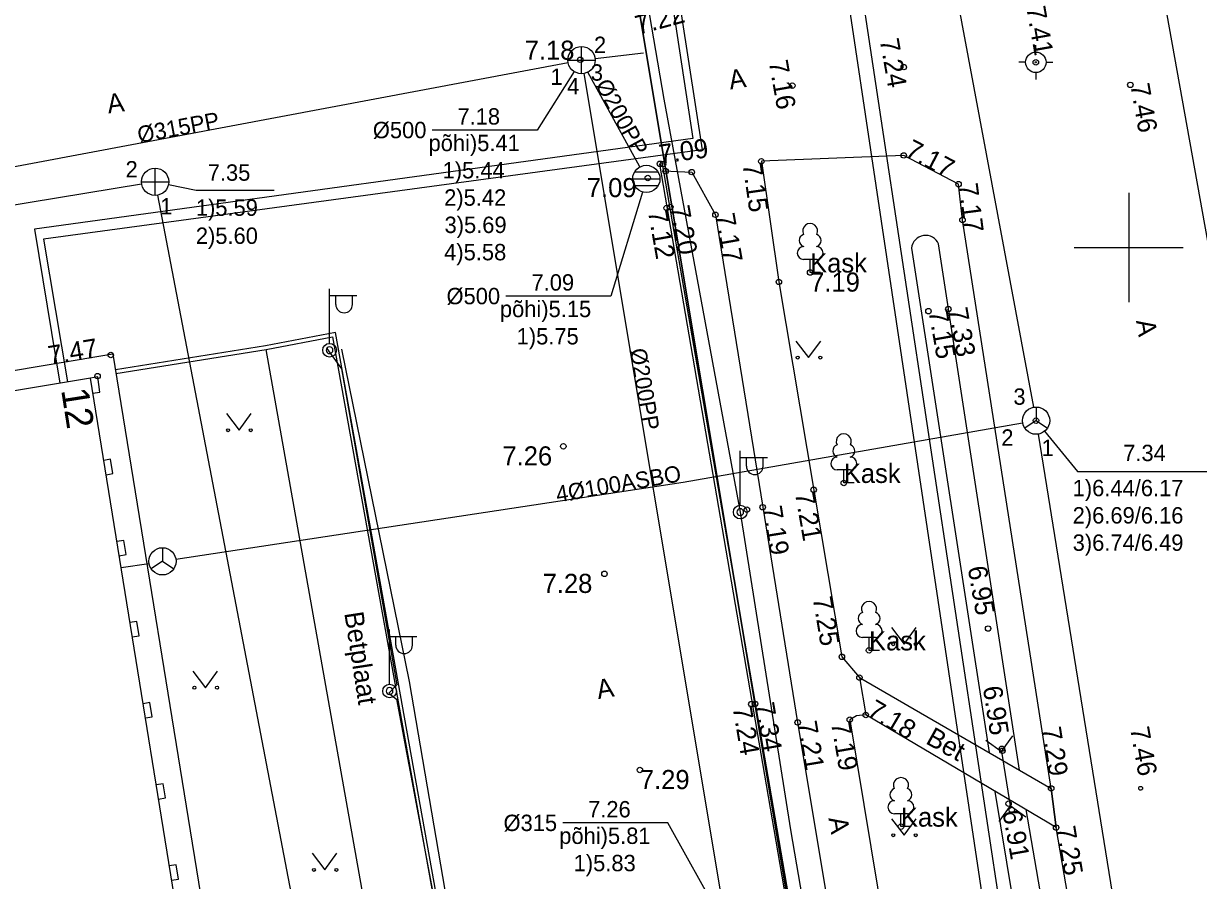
# Model space of a CAD drawing. Extents: x 473307 to 473719, y 6532843 to 6533381.
# Drawn here: x 473609.5 to 473652.56, y 6533026.81 to 6533058.21 of the extents above; entities that cross this region are included whole.
import ezdxf

# ---------------------------------------------------------------- set-up
doc = ezdxf.new("R2010")
doc.units = 0
for name, color, linetype in [('ALUSVORK', 7, 'Continuous'), ('Default', 7, 'Continuous'), ('HALJASTUS', 7, 'Continuous'), ('HOONE', 7, 'Continuous'), ('KKAEV', 7, 'Continuous'), ('KKAEV_NR', 7, 'Continuous'), ('KORGUS', 7, 'Continuous'), ('KTRASS', 7, 'Continuous'), ('MPKAABEL', 7, 'Continuous'), ('PIIR', 7, 'Continuous'), ('POST', 7, 'Continuous'), ('PUU', 7, 'Continuous'), ('SIKAEV', 7, 'Continuous'), ('SIKAEV_NR', 7, 'Continuous'), ('SITRASS', 7, 'Continuous'), ('SITRASS_TEKST', 7, 'Continuous'), ('SKKAEV', 7, 'Continuous'), ('SKKAEV_NR', 7, 'Continuous'), ('SKTRASS', 7, 'Continuous'), ('SKTRASS_TEKST', 7, 'Continuous'), ('TEE', 7, 'Continuous'), ('TRUUP', 7, 'Continuous'), ('TTRASS', 7, 'Continuous'), ('VEEKOGU', 7, 'Continuous'), ('VORK', 7, 'Continuous'), ('VTRASS', 7, 'Continuous')]:
    doc.layers.add(name, color=color, linetype=linetype)

# ---------------------------------------------------------------- blocks, each defined once
blk = doc.blocks.new('LEHTP1')
at = {"layer": 'Default'}
for p, q in [((0.48, 0.95), (-0.48, 0.95)), ((0, 0), (0, 0.95)), ((0.76, 0), (0, 0))]:
    blk.add_line(p, q, dxfattribs=at)
for centre, radius, start, end in [((0, 3.04), 0.554, 332.5799, 207.4201), ((-0.34, 2.345), 0.465, 109.02174, 253.14154), ((0.34, 2.345), 0.465, 286.85082, 70.98591), ((-0.475, 1.425), 0.475, 90.0016, 269.3953), ((0.475, 1.425), 0.475, 270.6047, 89.9984)]:
    blk.add_arc(centre, radius, start, end, dxfattribs=at)
blk = doc.blocks.new('SIKAEV')
at = {"layer": 'Default'}
for p, q in [((0, 1), (0, 0)), ((0, 0), (-0.83, -0.55)), ((0, 0), (0.83, -0.55))]:
    blk.add_line(p, q, dxfattribs=at)
blk.add_circle((0, 0), 1, dxfattribs=at)
blk = doc.blocks.new('MEPOST')
at = {"layer": 'Default'}
blk.add_circle((0, 0), 0.5, dxfattribs=at)
for start, end in [(0, 180), (180, 0)]:
    blk.add_arc((0, 0), 0.25, start, end, dxfattribs=at)
blk = doc.blocks.new('VAPOST')
at = {"layer": 'Default'}
for p, q in [((0, 0.5), (0, 4.5)), ((0, 4), (2, 4)), ((0.453, 3.358), (0.453, 4)), ((1.679, 3.358), (1.679, 4))]:
    blk.add_line(p, q, dxfattribs=at)
blk.add_arc((1.066, 3.358), 0.613, 180, 0, dxfattribs=at)
blk = doc.blocks.new('SPYMAR')
at = {"layer": 'Default'}
for p, q in [((0, 0.75), (0, 1.25)), ((-0.75, 0), (-1.25, 0)), ((0.75, 0), (1.25, 0)), ((0, -0.75), (0, -1.25))]:
    blk.add_line(p, q, dxfattribs=at)
for radius in [0.75, 0.044]:
    blk.add_circle((0, 0), radius, dxfattribs=at)
blk = doc.blocks.new('KAKAEV')
at = {"layer": 'Default'}
for p, q in [((0, -1), (0, 1)), ((-1, 0), (1, 0))]:
    blk.add_line(p, q, dxfattribs=at)
blk.add_circle((0, 0), 1, dxfattribs=at)
blk = doc.blocks.new('MURU')
at = {"layer": 'Default'}
for p, q in [((-0.927, 1.213), (0, 0)), ((0, 0), (0.891, 1.213))]:
    blk.add_line(p, q, dxfattribs=at)
for centre in [(-0.802, 0), (0.856, 0)]:
    blk.add_circle(centre, 0.11, dxfattribs=at)
blk = doc.blocks.new('REKAEV')
at = {"layer": 'Default'}
for p, q in [((-1, 0), (1, 0)), ((0.86, 0.5), (-0.86, 0.5)), ((0.86, -0.5), (-0.86, -0.5))]:
    blk.add_line(p, q, dxfattribs=at)
blk.add_circle((0, 0), 1, dxfattribs=at)
blk = doc.blocks.new('VKORIS')
at = {"layer": 'Default'}
for p, q in [((0, 4), (0, -4)), ((-4, 0), (4, 0))]:
    blk.add_line(p, q, dxfattribs=at)
blk = doc.blocks.new('TORVAL')
at = {"layer": 'Default'}
blk.add_lwpolyline([(-1, -1), (0, 0), (-1, 1)], dxfattribs=at)

msp = doc.modelspace()

# ---------------------------------------------------------------- linework, layer by layer
at = {"layer": 'HOONE'}
for points in [[(473618.421, 6532996.851), (473614.923, 6533017.718), (473616.359, 6533017.954), (473611.949, 6533045.219), (473599.157, 6533043.085), (473599.77, 6533039.408), (473600.209, 6533036.749), (473601.229, 6533030.585), (473603.062, 6533019.443), (473599.51, 6533018.858), (473603.372, 6532994.32), (473618.421, 6532996.851)], [(473612.039, 6533044.659), (473612.292, 6533044.7), (473612.216, 6533045.264), (473611.949, 6533045.219)], [(473612.522, 6533041.678), (473612.774, 6533041.719), (473612.69, 6533042.242), (473612.437, 6533042.201)], [(473613.002, 6533038.707), (473613.255, 6533038.748), (473613.17, 6533039.271), (473612.918, 6533039.23)], [(473613.483, 6533035.735), (473613.736, 6533035.776), (473613.651, 6533036.3), (473613.398, 6533036.259)], [(473613.964, 6533032.764), (473614.216, 6533032.805), (473614.132, 6533033.328), (473613.879, 6533033.287)], [(473614.444, 6533029.793), (473614.697, 6533029.834), (473614.612, 6533030.357), (473614.36, 6533030.316)], [(473614.925, 6533026.821), (473615.177, 6533026.862), (473615.093, 6533027.385), (473614.84, 6533027.345)]]:
    msp.add_lwpolyline(points, dxfattribs=at)
at = {"layer": 'KKAEV_NR'}
msp.add_lwpolyline([(473614.808, 6533052.312), (473615.827, 6533052.105), (473618.679, 6533052.105)], dxfattribs=at)
at = {"layer": 'KORGUS'}
for centre, radius in [((473629.899, 6533056.878), 0.1), ((473641.759, 6533056.61), 0.1), ((473646.598, 6533056.785), 0.1), ((473637.673, 6533055.928), 0.1), ((473650.059, 6533055.958), 0.1), ((473636.538, 6533053.158), 0.1), ((473641.759, 6533053.372), 0.1), ((473632.825, 6533053.066), 0.1), ((473632.932, 6533053.057), 0.1), ((473633.029, 6533052.8), 0.1), ((473633.987, 6533052.762), 0.1), ((473632.376, 6533052.545), 0.1), ((473643.766, 6533052.321), 0.1), ((473633.067, 6533051.448), 0.1), ((473633.203, 6533051.485), 0.1), ((473634.855, 6533051.199), 0.1), ((473643.91, 6533051.009), 0.1), ((473638.327, 6533049.085), 0.1), ((473637.182, 6533048.739), 0.1), ((473642.661, 6533047.668), 0.1), ((473643.391, 6533047.744), 0.1), ((473612.697, 6533046.062), 0.1), ((473612.21, 6533045.29), 0.1), ((473646.605, 6533043.657), 0.1), ((473629.282, 6533042.716), 0.1), ((473638.456, 6533041.123), 0.1), ((473639.559, 6533041.375), 0.1), ((473636.007, 6533040.397), 0.1), ((473636.587, 6533040.484), 0.1), ((473630.789, 6533038.045), 0.1), ((473644.847, 6533036.039), 0.1), ((473640.485, 6533035.24), 0.1), ((473639.489, 6533035.004), 0.1), ((473640.134, 6533034.243), 0.1), ((473636.17, 6533033.271), 0.1), ((473636.306, 6533033.279), 0.1), ((473640.364, 6533032.874), 0.1), ((473637.867, 6533032.601), 0.1), ((473639.778, 6533032.701), 0.1), ((473645.355, 6533031.637), 0.1), ((473645.373, 6533031.562), 0.1), ((473632.087, 6533030.859), 0.1), ((473647.159, 6533030.184), 0.1), ((473650.437, 6533030.188), 0.07), ((473645.597, 6533029.623), 0.1), ((473645.717, 6533029.391), 0.1), ((473641.654, 6533028.783), 0.1), ((473647.342, 6533028.748), 0.1)]:
    msp.add_circle(centre, radius, dxfattribs=at)
at = {"layer": 'KTRASS'}
for points in [[(473603.505, 6533050.637), (473613.825, 6533052.33)], [(473614.412, 6533051.92), (473622.17, 6533011.364)]]:
    msp.add_lwpolyline(points, dxfattribs=at)
at = {"layer": 'MPKAABEL'}
for points in [[(473630.644, 6533070.419), (473631.369, 6533064.793), (473632.97, 6533055.434), (473635.763, 6533040.307)], [(473631.369, 6533064.793), (473632.97, 6533055.434), (473635.763, 6533040.307), (473637.608, 6533028.672), (473640.108, 6533014.07), (473643.108, 6532999.199), (473645.16, 6532987.727), (473644.926, 6532986.565), (473645.46, 6532986.129), (473647.086, 6532975.076), (473649.618, 6532958.912)], [(473620.617, 6533046.296), (473621.149, 6533045.558), (473623.184, 6533033.982), (473622.885, 6533033.671), (473623.161, 6533033.456), (473625.425, 6533021.422), (473625.127, 6533020.991), (473625.392, 6533020.733), (473627.527, 6533008.94), (473627.41, 6533008.689), (473627.547, 6533008.477), (473629.153, 6532997.882), (473628.743, 6532997.831), (473628.458, 6532997.764), (473616.426, 6532995.506), (473605.82, 6532993.566), (473605.008, 6532993.105), (473595.487, 6532990.476)], [(473621.156, 6533046.272), (473623.63, 6533034.104), (473627.965, 6533008.739), (473629.773, 6532998.346), (473629.672, 6532997.664), (473629.313, 6532997.141), (473629.074, 6532996.947), (473617.704, 6532994.967), (473617.505, 6532995.424), (473617.231, 6532994.874), (473616.914, 6532994.828), (473605.877, 6532993.134), (473605.088, 6532993.085), (473595.487, 6532990.476)], [(473635.763, 6533040.307), (473637.608, 6533028.672), (473640.108, 6533014.07)]]:
    msp.add_lwpolyline(points, dxfattribs=at)
at = {"layer": 'PIIR'}
msp.add_lwpolyline([(473678.608, 6532842.593), (473677.66, 6532847.73), (473668.24, 6532906.4), (473664.64, 6532927.81), (473654.16, 6532926.37), (473630.89, 6533065.72), (473641.36, 6533067.51), (473636.3, 6533097.55), (473618.8, 6533170.64), (473609.94, 6533222.84), (473601.54, 6533272.81), (473599.09, 6533295.91), (473592.3, 6533328.43), (473587.14, 6533353.72), (473584.47, 6533353.28), (473580.56, 6533374.06), (473585.23, 6533374.14), (473584.699, 6533380.885)], dxfattribs=at)
msp.add_lwpolyline([(473486.57, 6533007.64), (473478.82, 6533017), (473548.5, 6533028.91), (473572.63, 6533056.43), (473618.6, 6533063.82), (473630.89, 6533065.72), (473654.16, 6532926.37), (473652.82, 6532924.82), (473637.7, 6532924.6), (473625.07, 6532926.73), (473607.63, 6532930.98), (473579.04, 6532941.93), (473554.34, 6532955.84), (473531.51, 6532970.21), (473509.62, 6532987.09)], close=True, dxfattribs=at)
at = {"layer": 'SIKAEV_NR'}
msp.add_lwpolyline([(473646.921, 6533043.269), (473648.12, 6533041.798), (473653.413, 6533041.798)], dxfattribs=at)
at = {"layer": 'SITRASS'}
for points in [[(473633.19, 6533115.473), (473646.517, 6533044.149)], [(473615.081, 6533038.578), (473633.678, 6533041.408), (473646.112, 6533043.571)], [(473646.684, 6533043.163), (473655.476, 6532988.623)], [(473613.082, 6533038.274), (473614.093, 6533038.428)]]:
    msp.add_lwpolyline(points, dxfattribs=at)
at = {"layer": 'SKKAEV_NR'}
for points in [[(473629.678, 6533056.445), (473628.327, 6533054.304), (473624.472, 6533054.304)], [(473632.179, 6533052.033), (473631.028, 6533048.221), (473627.173, 6533048.221)], [(473635.024, 6533025.477), (473633.116, 6533028.921), (473629.261, 6533028.921)]]:
    msp.add_lwpolyline(points, dxfattribs=at)
at = {"layer": 'SKTRASS'}
msp.add_line((473630.027, 6533056.375), (473635.184, 6533025.533), dxfattribs=at)
for points in [[(473630.442, 6533056.925), (473632.225, 6533057.129)], [(473586.928, 6533048.79), (473629.454, 6533056.776)], [(473632.083, 6533052.951), (473630.185, 6533056.429)]]:
    msp.add_lwpolyline(points, dxfattribs=at)
at = {"layer": 'TEE'}
for q in [(473607.372, 6533045.193), (473617.355, 6533017.894)]:
    msp.add_line((473612.772, 6533046.091), q, dxfattribs=at)
for points in [[(473651.595, 6533003.976), (473647.342, 6533028.748), (473647.159, 6533030.184), (473643.91, 6533051.009), (473643.766, 6533052.321), (473641.759, 6533053.372), (473636.538, 6533053.158), (473637.182, 6533048.739), (473639.489, 6533035.004), (473640.134, 6533034.243), (473640.364, 6533032.874), (473640.02, 6533032.843), (473639.778, 6533032.701), (473641.567, 6533021.908), (473642.795, 6533014.249), (473643.8, 6533008.263), (473644.648, 6533002.267)], [(473612.887, 6533045.386), (473618.389, 6533046.267), (473620.827, 6533046.733), (473624.654, 6533025.417), (473627.123, 6533011.412), (473639.58, 6533013.602), (473640.003, 6533011.142), (473627.561, 6533008.964), (473629.35, 6532998.768), (473641.884, 6533000.96), (473636.91, 6533029.908), (473632.921, 6533053.063), (473632.802, 6533053.048), (473636.782, 6533029.886), (473639.558, 6533013.731), (473632.112, 6533012.421), (473629.669, 6533026.279), (473624.782, 6533025.439), (473620.932, 6533046.885), (473618.367, 6533046.395), (473612.866, 6533045.514)], [(473632.968, 6533052.808), (473633.987, 6533052.762), (473634.855, 6533051.199), (473636.587, 6533040.484), (473637.867, 6533032.601), (473639.562, 6533022.421), (473640.864, 6533013.856)], [(473614.962, 6533017.483), (473623.249, 6533018.905), (473622.268, 6533024.462), (473618.392, 6533046.267)], [(473640.133, 6533034.25), (473647.159, 6533030.184), (473647.342, 6533028.748), (473640.364, 6533032.874)]]:
    msp.add_lwpolyline(points, dxfattribs=at)
at = {"layer": 'TRUUP'}
msp.add_lwpolyline([(473645.341, 6533031.538), (473645.654, 6533029.541)], dxfattribs=at)
at = {"layer": 'TTRASS'}
for points in [[(473670.739, 6532903.73), (473669.823, 6532910.623), (473662.59, 6532909.156), (473646.821, 6533011.679), (473633.537, 6533100.476), (473633.406, 6533101.178), (473632.559, 6533105.696), (473632.32, 6533106.603), (473631.402, 6533106.697), (473628.136, 6533106.491), (473627.343, 6533106.38), (473626.399, 6533106.377), (473626.238, 6533107.261), (473626.052, 6533109.168), (473625.777, 6533111.724), (473625.749, 6533112.421), (473625.73, 6533112.829)], [(473671.344, 6532903.733), (473670.333, 6532911.339), (473663.087, 6532909.869), (473647.414, 6533011.77), (473634.242, 6533098.966), (473634.072, 6533100.094), (473632.984, 6533106.198), (473632.738, 6533107.055), (473631.832, 6533107.173), (473627.702, 6533106.877), (473626.788, 6533106.911), (473626.656, 6533107.813), (473626.548, 6533108.653), (473626.413, 6533111.755), (473626.375, 6533112.253)], [(473633.406, 6533101.178), (473633.081, 6533101.127), (473632.304, 6533100.979), (473630.856, 6533100.78), (473627.479, 6533100.247), (473626.609, 6533099.957), (473626.743, 6533099.051), (473630.267, 6533078.738), (473630.267, 6533078.738), (473634.025, 6533053.988), (473634.025, 6533053.988), (473609.897, 6533050.671), (473609.897, 6533050.671), (473610.826, 6533045.035)], [(473633.938, 6533100.847), (473633.59, 6533100.802), (473632.304, 6533100.574), (473630.879, 6533100.354), (473627.869, 6533099.885), (473626.941, 6533099.623), (473627.036, 6533098.737), (473630.55, 6533078.344), (473630.55, 6533078.344), (473634.37, 6533053.573), (473634.37, 6533053.573), (473610.226, 6533050.303), (473610.226, 6533050.303), (473611.111, 6533045.083)]]:
    msp.add_lwpolyline(points, dxfattribs=at)
at = {"layer": 'VEEKOGU'}
for points in [[(473642.044, 6533049.977), (473644.887, 6533031.499)], [(473645.997, 6533030.856), (473643.032, 6533050.129)], [(473646.228, 6533029.407), (473648.092, 6533018.623), (473650.626, 6533003.631), (473649.236, 6533003.443), (473647.022, 6533018.462), (473645.105, 6533030.071)]]:
    msp.add_lwpolyline(points, dxfattribs=at)
msp.add_arc((473642.557, 6533049.928), 0.516, 22.9765, 174.5171, dxfattribs=at)
at = {"layer": 'VTRASS'}
msp.add_lwpolyline([(473650.187, 6533065.267), (473656.972, 6533027.535), (473675.322, 6532917.037), (473677.26, 6532903.765)], dxfattribs=at)

# ---------------------------------------------------------------- block references
at = {"layer": 'ALUSVORK', "xscale": 0.5, "yscale": 0.5}
msp.add_blockref('SPYMAR', (473646.598, 6533056.785), dxfattribs=at)
at = {"layer": 'HALJASTUS', "xscale": 0.5, "yscale": 0.5}
for p in [(473638.271, 6533045.967), (473617.397, 6533043.307), (473641.771, 6533035.467), (473616.162, 6533033.874), (473641.771, 6533028.467), (473620.54, 6533027.2)]:
    msp.add_blockref('MURU', p, dxfattribs=at)
at = {"layer": 'KKAEV', "xscale": 0.5, "yscale": 0.5}
msp.add_blockref('KAKAEV', (473614.318, 6533052.411), dxfattribs=at)
at = {"layer": 'POST', "xscale": 0.5, "yscale": 0.5}
for name, p in [('VAPOST', (473620.714, 6533046.237)), ('MEPOST', (473620.714, 6533046.237)), ('VAPOST', (473635.763, 6533040.307)), ('MEPOST', (473635.763, 6533040.307)), ('VAPOST', (473622.912, 6533033.751)), ('MEPOST', (473622.912, 6533033.751))]:
    msp.add_blockref(name, p, dxfattribs=at)
at = {"layer": 'PUU', "xscale": 0.5, "yscale": 0.5}
for p in [(473638.327, 6533049.085), (473639.559, 6533041.375), (473640.485, 6533035.24), (473641.654, 6533028.783)]:
    msp.add_blockref('LEHTP1', p, dxfattribs=at)
at = {"layer": 'SIKAEV', "xscale": 0.5, "yscale": 0.5}
for p in [(473646.605, 6533043.657), (473614.587, 6533038.503)]:
    msp.add_blockref('SIKAEV', p, dxfattribs=at)
at = {"layer": 'SKKAEV', "xscale": 0.5, "yscale": 0.5}
for name, p in [('KAKAEV', (473629.945, 6533056.868)), ('REKAEV', (473632.323, 6533052.512))]:
    msp.add_blockref(name, p, dxfattribs=at)
at = {"layer": 'TRUUP'}
for p, xscale, yscale, rotation in [((473645.341, 6533031.538), 0.4999999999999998, 0.49999999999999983, -81.09198438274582), ((473645.654, 6533029.541), 0.49999999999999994, 0.49999999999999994, 98.90801561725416)]:
    msp.add_blockref('TORVAL', p, dxfattribs=dict(at, xscale=xscale, yscale=yscale, rotation=rotation))
at = {"layer": 'VORK', "xscale": 0.5, "yscale": 0.5}
msp.add_blockref('VKORIS', (473650, 6533050), dxfattribs=at)

# ---------------------------------------------------------------- texts
at = {"layer": 'HOONE'}
msp.add_text('12', height=1, rotation=278.878, dxfattribs=at).set_placement((473610.876, 6533044.781))
at = {"layer": 'KKAEV_NR'}
for s, p in [('2', (473613.237, 6533052.567)), ('7.35', (473616.249, 6533052.446)), ('1', (473614.511, 6533051.214)), ('1)5.59', (473615.813, 6533051.161)), ('2)5.60', (473615.813, 6533050.132))]:
    msp.add_text(s, height=0.6, dxfattribs=at).set_placement(p)
at = {"layer": 'KORGUS'}
for s, rotation, p in [('7.22', 15.1972, (473632.027, 6533057.788)), ('7.41', 280, (473646.245, 6533058.787)), ('7.24', 280, (473640.873, 6533057.605)), ('7.16', 280, (473636.807, 6533056.808)), ('7.46', 280, (473650.059, 6533055.958)), ('7.09', 7.6494, (473632.825, 6533053.066)), ('7.17', 332.3604, (473641.759, 6533053.372)), ('7.15', 278.2916, (473635.845, 6533053.057)), ('7.17', 277.3557, (473643.766, 6533052.321)), ('7.20', 279.9402, (473633.203, 6533051.485)), ('7.12', 279.9402, (473632.378, 6533051.327)), ('7.17', 280, (473634.855, 6533051.199)), ('7.15', 280, (473642.661, 6533047.668)), ('7.33', 280, (473643.391, 6533047.744)), ('7.47', 9.4427, (473610.461, 6533045.69)), ('7.21', 279.8397, (473637.766, 6533041.003)), ('7.19', 279.2229, (473636.587, 6533040.484)), ('6.95', 280, (473644.097, 6533038.276)), ('7.25', 279.5347, (473638.418, 6533037.156)), ('6.95', 278.7468, (473644.654, 6533033.89)), ('7.18', 329.4047, (473640.364, 6533032.874)), ('7.24', 279.7504, (473635.48, 6533033.152)), ('7.34', 279.7504, (473636.306, 6533033.279)), ('7.21', 279.4532, (473637.867, 6533032.601)), ('7.19', 279.8496, (473639.088, 6533032.581)), ('7.29', 278.8675, (473646.815, 6533032.391)), ('7.46', 280, (473650.049, 6533032.387)), ('6.91', 280, (473645.372, 6533029.33)), ('7.25', 279.7419, (473647.342, 6533028.748))]:
    msp.add_text(s, height=0.7, rotation=rotation, dxfattribs=at).set_placement(p)
for s, p in [('7.18', (473627.866, 6533056.878)), ('7.09', (473630.143, 6533051.845)), ('7.19', (473638.327, 6533048.385)), ('7.26', (473627.049, 6533042.016)), ('7.28', (473628.522, 6533037.345)), ('7.29', (473632.087, 6533030.159))]:
    msp.add_text(s, height=0.7, dxfattribs=at).set_placement(p)
at = {"layer": 'PUU'}
for p in [(473638.327, 6533049.085), (473639.559, 6533041.375), (473640.485, 6533035.24), (473641.654, 6533028.783)]:
    msp.add_text('Kask', height=0.7, dxfattribs=at).set_placement(p)
at = {"layer": 'SIKAEV_NR'}
for s, p in [('3', (473645.775, 6533044.238)), ('2', (473645.333, 6533042.738)), ('1', (473646.806, 6533042.361)), ('7.34', (473649.799, 6533042.174)), ('1)6.44/6.17', (473647.948, 6533040.888)), ('2)6.69/6.16', (473647.948, 6533039.888)), ('3)6.74/6.49', (473647.948, 6533038.888))]:
    msp.add_text(s, height=0.6, dxfattribs=at).set_placement(p)
at = {"layer": 'SITRASS_TEKST'}
msp.add_text('4%%c100ASBO', height=0.6, rotation=9.7117, dxfattribs=at).set_placement((473629.063, 6533040.658))
at = {"layer": 'SKKAEV_NR'}
for s, p in [('2', (473630.404, 6533057.125)), ('3', (473630.29, 6533056.112)), ('1', (473628.808, 6533055.956)), ('4', (473629.421, 6533055.613)), ('7.18', (473625.4, 6533054.504)), ('%%C500', (473622.301, 6533054.004)), ('põhi)5.41', (473624.342, 6533053.531)), ('1)5.44', (473624.857, 6533052.531)), ('2)5.42', (473624.914, 6533051.531)), ('3)5.69', (473624.928, 6533050.531)), ('4)5.58', (473624.914, 6533049.531)), ('7.09', (473628.115, 6533048.421)), ('%%C500', (473625.001, 6533047.921)), ('põhi)5.15', (473626.957, 6533047.449)), ('1)5.75', (473627.572, 6533046.449)), ('7.26', (473630.189, 6533029.121)), ('%%C315', (473627.09, 6533028.621)), ('põhi)5.81', (473629.132, 6533028.149)), ('1)5.83', (473629.66, 6533027.149))]:
    msp.add_text(s, height=0.6, dxfattribs=at).set_placement(p)
at = {"layer": 'SKTRASS_TEKST'}
for s, rotation, p in [('%%C200PP', 298.6307, (473630.435, 6533055.97)), ('%%C315PP', 10.6352, (473613.734, 6533053.824)), ('%%C200PP', 279.4909, (473631.719, 6533046.259))]:
    msp.add_text(s, height=0.6, rotation=rotation, dxfattribs=at).set_placement(p)
at = {"layer": 'TEE'}
for s, rotation, p in [('A', 9.022, (473635.398, 6533055.787)), ('A', 7.7145, (473612.607, 6533054.91)), ('A', 279.4431, (473650.267, 6533047.316)), ('Betplaat', 278.7908, (473621.252, 6533036.607)), ('A', 9.7663, (473630.56, 6533033.453)), ('Bet', 330.9025, (473642.523, 6533031.848)), ('A', 279.8396, (473638.994, 6533029.092))]:
    msp.add_text(s, height=0.7, rotation=rotation, dxfattribs=at).set_placement(p)

doc.saveas('drawing.dxf')
